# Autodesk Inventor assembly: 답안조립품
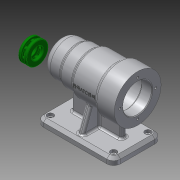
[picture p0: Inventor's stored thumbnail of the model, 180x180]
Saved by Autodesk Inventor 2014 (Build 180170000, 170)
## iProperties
Created: 2016-06
Part Number: 답안조립품
Document SubType Name: Assembly
Designer: USER
Author: USER
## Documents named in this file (3)
- C:\Users\USER\Desktop\460607V1026\답안조립품.iam
- C:\Users\USER\Desktop\460607V1026\본체.ipt
- C:\Users\USER\Desktop\460607V1026\베어링 51202.ipt
